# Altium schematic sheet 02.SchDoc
size 299 x 210 mm
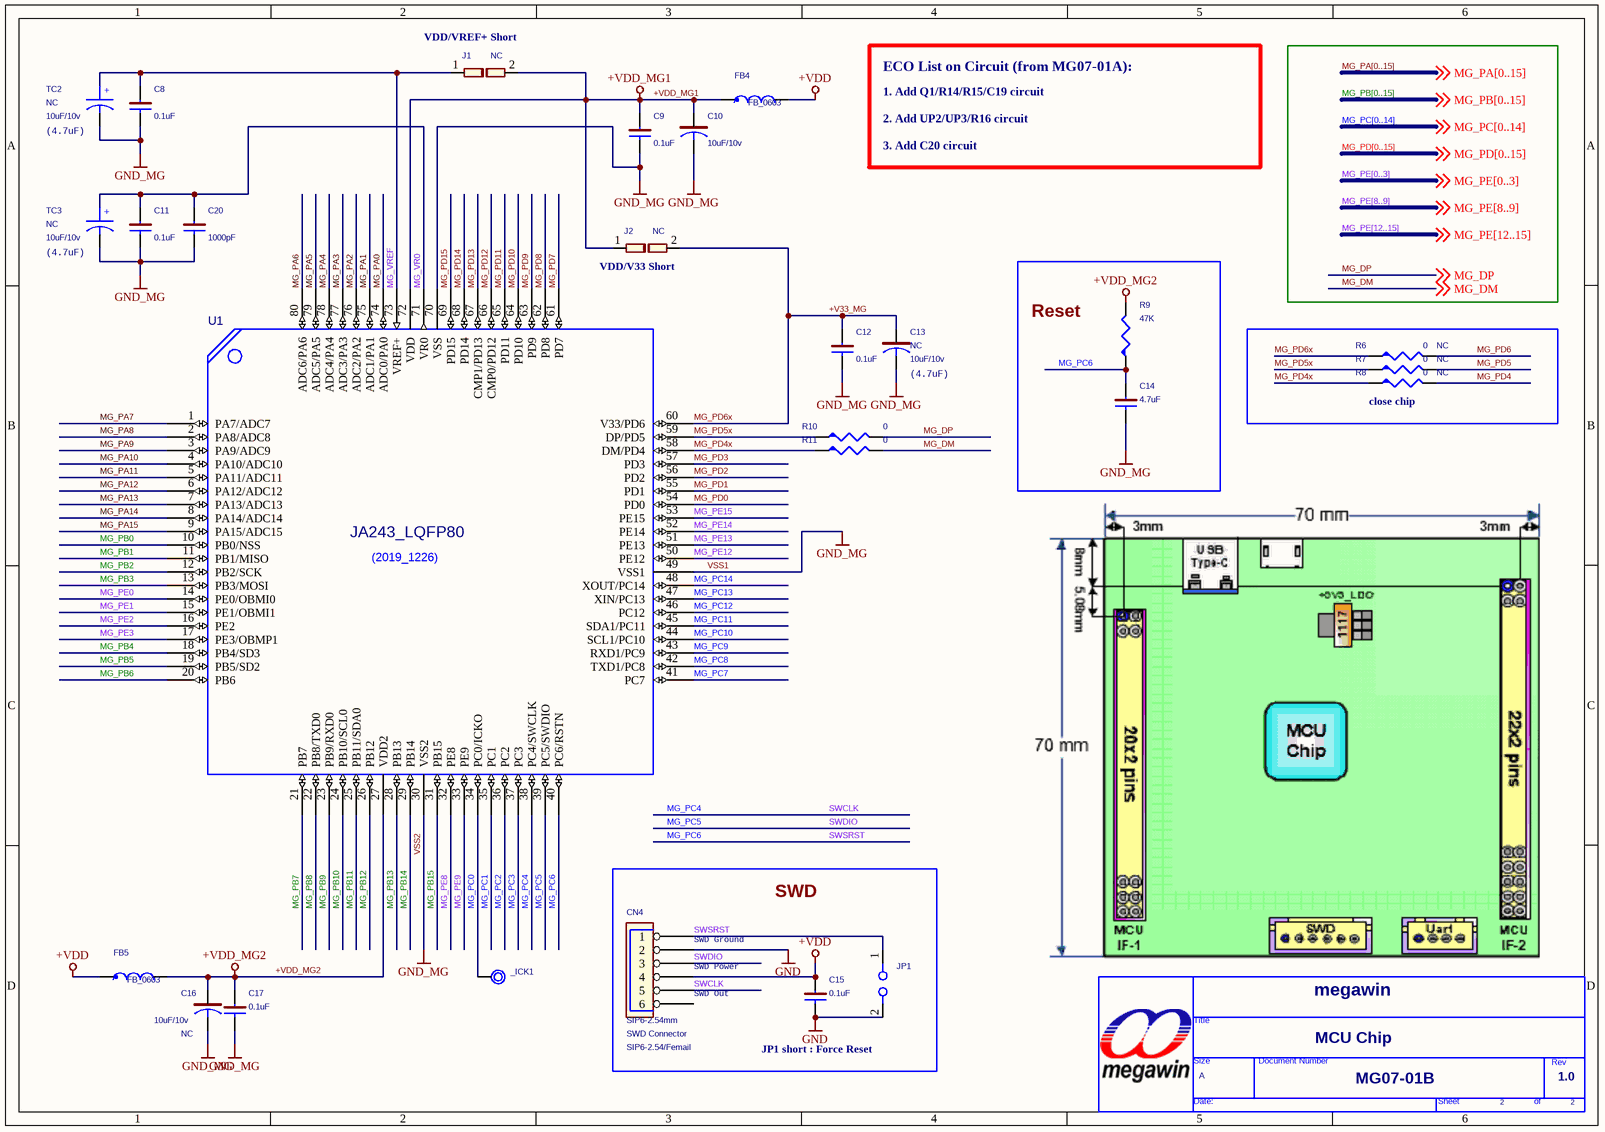
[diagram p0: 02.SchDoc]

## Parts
*  OrgName: megawin  Doc: MG07-01B  RevCode: 1.0  Title: MCU Chip  Page Size: A  Page Number: 2  (hidden comment: TitleBlock_MegaWin)  (graphical)
_ICK1  TP-COIL  [TPH60-COIL]  (value not drawn)
C8  0.1uF  [C-0603]
C9  0.1uF  [C-0603]
C10  10uF/10v  [C-0805]
C11  0.1uF  [C-0603]
C12  0.1uF  [C-0603]
C13  10uF/10v  Assembly: NC  [C-0805]
C14  4.7uF  [C-0603]
C15  0.1uF  [C-0603]
C16  10uF/10v  Assembly: NC  [C-0805]
C17  0.1uF  [C-0603]
C20  1000pF  [C-0603]
CN4  SIP6-2.54mm  Package: SIP6-2.54/Femail  Function: SWD Connector  [HD6-P2.54-UL]
FB4  FB_0603  [L-0603]
FB5  FB_0603  [L-0603]
J1  Assembly: NC  [JUNCTION-0603]  (hidden comment: JUNCTION_0603)
J2  Assembly: NC  [JUNCTION-0603]  (hidden comment: JUNCTION_0603)
JP1  JUMPER  [SIP2-P2.54]  (value not drawn)
R6  0  Assembly: NC  [R-0603]
R7  0  Assembly: NC  [R-0603]
R8  0  Assembly: NC  [R-0603]
R9  47K  [R-0603]
R10  0  [R-0603]
R11  0  [R-0603]
TC2  10uF/10v  Assembly: NC  [C-1210+]
TC3  10uF/10v  Assembly: NC  [C-1210+]
U1  JA243_LQFP80  [QFP80-P0.4-Z12X12]

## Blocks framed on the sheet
Reset: C14 R9
close chip: R6-R8
SWD: C15 CN4 JP1

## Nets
+VDD: C15.1 CN4.4 FB4.2 FB5.1
+VDD_MG1: C9.1 C10.1 FB4.1 J1.2(JP2) J2.1(JP1) U1.72(VDD)
+VDD_MG2: C16.1 C17.1 FB5.2 R9.2 U1.27(VDD2)
GND: C15.2 CN4.2 JP1.2
VSS1: C8.2 C9.2 C10.2 C11.2 C12.2 C13.2 C14.2 C16.2 C17.2 C20.2 TC2.2 TC3.2 U1.30(VSS2) U1.49(VSS1) U1.70(VSS)  [also labelled GND_MG, VSS2]
+V33_MG: C12.1 C13.1 J2.2(JP2) R6.1 U1.60(V33/PD6)  [also labelled MG_PD6x]
MG_DM: R11.2 ; off-sheet MG_DM
MG_DP: R10.2 ; off-sheet MG_DP
MG_PA0: U1.74(ADC0/PA0)
MG_PA1: U1.75(ADC1/PA1)
MG_PA2: U1.76(ADC2/PA2)
MG_PA3: U1.77(ADC3/PA3)
MG_PA4: U1.78(ADC4/PA4)
MG_PA5: U1.79(ADC5/PA5)
MG_PA6: U1.80(ADC6/PA6)
MG_PA7: U1.1(PA7/ADC7)
MG_PA8: U1.2(PA8/ADC8)
MG_PA9: U1.3(PA9/ADC9)
MG_PA10: U1.4(PA10/ADC10)
MG_PA11: U1.5(PA11/ADC11)
MG_PA12: U1.6(PA12/ADC12)
MG_PA13: U1.7(PA13/ADC13)
MG_PA14: U1.8(PA14/ADC14)
MG_PA15: U1.9(PA15/ADC15)
MG_PB0: U1.10(PB0/NSS)
MG_PB1: U1.11(PB1/MISO)
MG_PB2: U1.12(PB2/SCK)
MG_PB3: U1.13(PB3/MOSI)
MG_PB4: U1.18(PB4/SD3)
MG_PB5: U1.19(PB5/SD2)
MG_PB6: U1.20(PB6)
MG_PB7: U1.21(PB7)
MG_PB8: U1.22(PB8/TXD0)
MG_PB9: U1.23(PB9/RXD0)
MG_PB10: U1.24(PB10/SCL0)
MG_PB11: U1.25(PB11/SDA0)
MG_PB12: U1.26(PB12)
MG_PB13: U1.28(PB13)
MG_PB14: U1.29(PB14)
MG_PB15: U1.31(PB15)
MG_PC0: _ICK1.1 U1.34(PC0/ICKO)
MG_PC1: U1.35(PC1)
MG_PC2: U1.36(PC2)
MG_PC3: U1.37(PC3)
MG_PC4: CN4.5 U1.38(PC4/SWCLK)  [also labelled SWCLK]
MG_PC5: CN4.3 U1.39(PC5/SWDIO)  [also labelled SWDIO]
MG_PC6: C14.1 CN4.1 JP1.1 R9.1 U1.40(PC6/RSTN)  [also labelled SWSRST]
MG_PC7: U1.41(PC7)
MG_PC8: U1.42(TXD1/PC8)
MG_PC9: U1.43(RXD1/PC9)
MG_PC10: U1.44(SCL1/PC10)
MG_PC11: U1.45(SDA1/PC11)
MG_PC12: U1.46(PC12)
MG_PC13: U1.47(XIN/PC13)
MG_PC14: U1.48(XOUT/PC14)
MG_PD0: U1.54(PD0)
MG_PD1: U1.55(PD1)
MG_PD2: U1.56(PD2)
MG_PD3: U1.57(PD3)
MG_PD4: R8.2
MG_PD4x: R8.1 R11.1 U1.58(DM/PD4)
MG_PD5: R7.2
MG_PD5x: R7.1 R10.1 U1.59(DP/PD5)
MG_PD6: R6.2
MG_PD7: U1.61(PD7)
MG_PD8: U1.62(PD8)
MG_PD9: U1.63(PD9)
MG_PD10: U1.64(PD10)
MG_PD11: U1.65(PD11)
MG_PD12: U1.66(CMP0/PD12)
MG_PD13: U1.67(CMP1/PD13)
MG_PD14: U1.68(PD14)
MG_PD15: U1.69(PD15)
MG_PE0: U1.14(PE0/OBMI0)
MG_PE1: U1.15(PE1/OBMI1)
MG_PE2: U1.16(PE2)
MG_PE3: U1.17(PE3/OBMP1)
MG_PE8: U1.32(PE8)
MG_PE9: U1.33(PE9)
MG_PE12: U1.50(PE12)
MG_PE13: U1.51(PE13)
MG_PE14: U1.52(PE14)
MG_PE15: U1.53(PE15)
MG_VR0: C11.1 C20.1 TC3.1 U1.71(VR0)
MG_VREF: C8.1 J1.1(JP1) TC2.1 U1.73(VREF+)

Not connected (* = marked no-connect by the designer): CN4 6

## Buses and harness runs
bus MG_PA[0..15]
bus MG_PB[0..15]
bus MG_PC[0..14]
bus MG_PD[0..15]
bus MG_PE[0..3]
bus MG_PE[8..9]
bus MG_PE[12..15]

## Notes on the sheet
- (near J1) VDD/VREF+ Short
- ECO List on Circuit (from MG07-01A):
- (near TC2) (4.7uF)
- 1. Add Q1/R14/R15/C19 circuit
- 2. Add UP2/UP3/R16 circuit
- 3. Add C20 circuit
- (near TC3) (4.7uF)
- (near J2) VDD/V33 Short
- (near C13) (4.7uF)
- (near CN4) SWD Ground
- (near CN4) SWD Power
- (near CN4) SWD Out
- JP1 short : Force Reset

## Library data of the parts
_ICK1 = TPH60-COIL: Assembly: NC
C8 C9 C11 C12 C14 C15 C17 C20 = CAP-NP
C10 C13 C16 = CAP-POL
CN4 = SIP6
FB4 FB5 = FB2
R6-R8 R10 R11 = R: 2ND PART FIELD: SMD_0805
R9 = R
TC2 TC3 = CAP-EC
U1 = IC-MG32F02A128-LQFP80: Designator: A; OriginalSymbolOrigin: (0,0); SWAP_INFO: (S1+S2); SPLIT_INST: TRUE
